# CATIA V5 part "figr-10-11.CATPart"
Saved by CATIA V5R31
Part number: Part1
Bounding box of the stored display mesh (mm): x -100 to 0, y -100 to 90, z 0 to 33.608
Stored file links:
  D:\PROJECTS\Project 2021\US EDITION\CATIA V5 6R 2021\Resources\Part Files\c10_catia_v5_6r2021_prt\c10_catia_v5_6r2021_prt\figr-10-11.CATPart
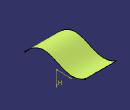
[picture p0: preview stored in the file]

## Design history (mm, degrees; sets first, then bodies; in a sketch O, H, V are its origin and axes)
Set1
  Sketch1 on face of yz-plane, origin (0, 0, 0), H (0, 0, -1), V (0, 1, 0)
    spline S1 through (0, -100) (-30, -20) (-10, 30) (-20, 90)
  Extrude1: Element1 Sketch1, Lim1 0, Lim2 100, Direction face of yz-plane
Body1 (main body)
